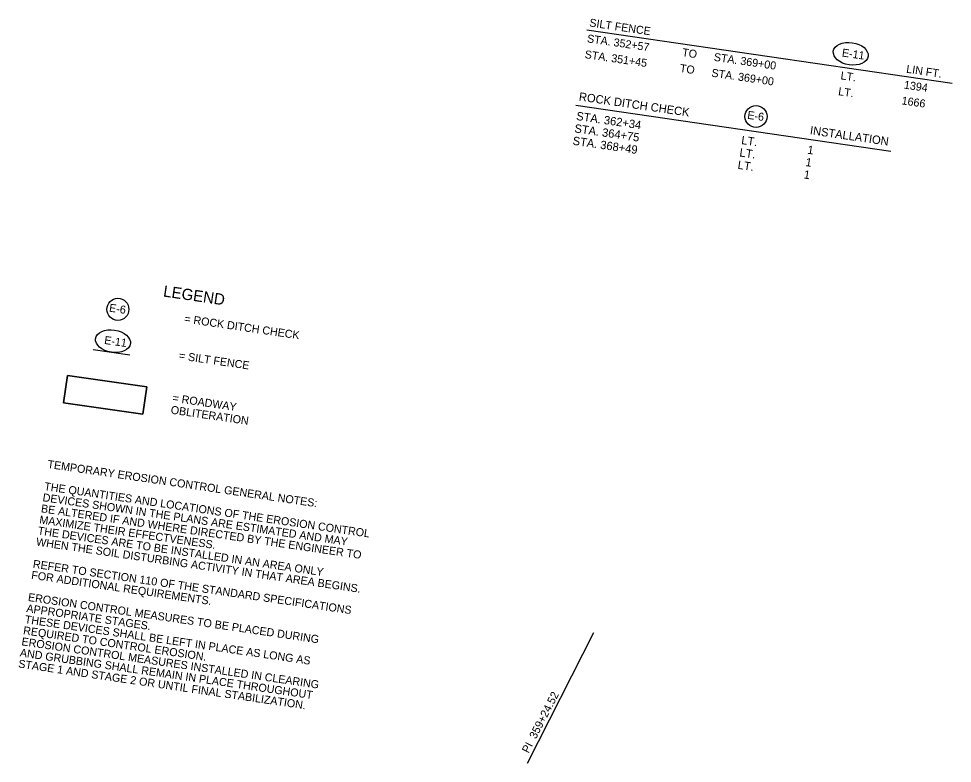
# Model space of a CAD drawing. Extents: x 882623 to 886086, y 1564278 to 1565583.
# Drawn here: x 884408 to 885107, y 1564440 to 1564998 of the extents above; entities that cross this region are included whole.
import ezdxf

# ---------------------------------------------------------------- set-up
doc = ezdxf.new("R2010")
doc.units = 0
for name, color, linetype in [('R_Annotation', 7, 'Continuous'), ('R_Draft', 7, 'Continuous'), ('R_Erosion', 7, 'Continuous'), ('R_Erosion_STG 2', 7, 'Continuous'), ('R_Horz Alg Annot', 7, 'Continuous')]:
    doc.layers.add(name, color=color, linetype=linetype)

msp = doc.modelspace()

# ---------------------------------------------------------------- linework, layer by layer
at = {"layer": 'R_Annotation'}
msp.add_line((884833.55, 1564989.99), (885107.46, 1564949.97), dxfattribs=at)
msp.add_lwpolyline([(884444.52, 1564731.01), (884503.77, 1564722.35), (884500.77, 1564701.85), (884441.52, 1564710.51)], close=True, dxfattribs=at)
at = {"layer": 'R_Draft'}
msp.add_lwpolyline([(884441.52, 1564710.51), (884500.77, 1564701.85), (884503.77, 1564722.35), (884444.52, 1564731.01), (884441.52, 1564710.51)], dxfattribs=at)
at = {"layer": 'R_Erosion'}
msp.add_lwpolyline([(884463.58, 1564750.33), (884491.09, 1564746.31)], dxfattribs=at)
for centre in [(884960.36, 1564925.1), (884482.16, 1564780.51)]:
    msp.add_circle(centre, 8.26, dxfattribs=at)
for centre in [(885031.3, 1564972.14), (884478.52, 1564756.64)]:
    msp.add_ellipse(centre, major_axis=(13.02, -1.85), ratio=0.638788, dxfattribs=at)
at = {"layer": 'R_Erosion_STG 2'}
msp.add_line((884825.45, 1564933.69), (885061.31, 1564899.23), dxfattribs=at)
at = {"layer": 'R_Horz Alg Annot'}
msp.add_lwpolyline([(884838.65, 1564537.97), (884788.78, 1564440.11)], dxfattribs=at)

# ---------------------------------------------------------------- texts
at = {"layer": 'R_Annotation'}
for s, p in [('SILT FENCE', (884835.17, 1564992.68)), ('STA. 352+57 ', (884833.43, 1564980.8)), ('STA. 351+45', (884831.7, 1564968.93)), ('TO', (884904.68, 1564970.4)), ('STA. 369+00', (884928.43, 1564966.93)), ('TO', (884902.94, 1564958.52)), ('LIN FT. ', (885072.65, 1564957.98)), ('STA. 369+00', (884926.69, 1564955.05)), ('LT.', (885023.42, 1564953.05)), ('1394', (885070.91, 1564946.11)), ('LT.', (885021.68, 1564941.17)), ('1666', (885069.18, 1564934.24)), ('TEMPORARY EROSION CONTROL GENERAL NOTES:', (884429.12, 1564661.65)), ('THE QUANTITIES AND LOCATIONS OF THE EROSION CONTROL', (884426.69, 1564645.02)), ('DEVICES SHOWN IN THE PLANS ARE ESTIMATED AND MAY', (884425.48, 1564636.71)), ('BE ALTERED IF AND WHERE DIRECTED BY THE ENGINEER TO', (884424.27, 1564628.4)), ('MAXIMIZE THEIR EFFECTVENESS.', (884423.05, 1564620.09)), ('THE DEVICES ARE TO BE INSTALLED IN AN AREA ONLY', (884421.84, 1564611.78)), ('WHEN THE SOIL DISTURBING ACTIVITY IN THAT AREA BEGINS.', (884420.62, 1564603.46)), ('REFER TO SECTION 110 OF THE STANDARD SPECIFICATIONS', (884418.19, 1564586.84)), ('FOR ADDITIONAL REQUIREMENTS.', (884416.98, 1564578.53)), ('EROSION CONTROL MEASURES TO BE PLACED DURING', (884414.55, 1564561.91)), ('APPROPRIATE STAGES. ', (884413.34, 1564553.59)), ('THESE DEVICES SHALL BE LEFT IN PLACE AS LONG AS', (884412.12, 1564545.28)), ('REQUIRED TO CONTROL EROSION.', (884410.91, 1564536.97)), ('EROSION CONTROL MEASURES INSTALLED IN CLEARING', (884409.69, 1564528.66)), ('AND GRUBBING SHALL REMAIN IN PLACE THROUGHOUT', (884408.48, 1564520.35)), ('STAGE 1 AND STAGE 2 OR UNTIL FINAL STABILIZATION.', (884407.27, 1564512.04))]:
    msp.add_text(s, height=6, rotation=351.68808, dxfattribs=at).set_placement(p)
at = {"layer": 'R_Erosion'}
for s, height, rotation, p in [('E-11', 5.999, 351.90245, (885024.45, 1564970.13)), ('E-6 ', 5.999, 352.08863, (884953.56, 1564923.41)), ('LEGEND', 8.439, 351.68809, (884515.78, 1564790.18)), ('E-6 ', 5.999, 352.08863, (884475.36, 1564778.82)), ('= ROCK DITCH CHECK', 6, 351.68809, (884531.63, 1564770.66)), ('E-11', 5.999, 351.90245, (884471.67, 1564754.63)), ('= SILT FENCE', 6, 351.68809, (884527.6, 1564743.07)), ('= ROADWAY ', 6, 351.68809, (884522.8, 1564711.29)), ('OBLITERATION', 6, 351.68809, (884521.5, 1564702.38))]:
    msp.add_text(s, height=height, rotation=rotation, dxfattribs=at).set_placement(p)
at = {"layer": 'R_Erosion_STG 2'}
for s, p in [('ROCK DITCH CHECK', (884827.33, 1564937.13)), ('STA. 362+34', (884825.34, 1564922.56)), ('STA. 364+75', (884823.98, 1564913.29)), ('INSTALLATION', (885000.49, 1564911.83)), ('STA. 368+49', (884822.63, 1564904.01)), ('LT.', (884949.02, 1564904.49)), ('LT.', (884947.67, 1564895.22)), ('1', (884998.5, 1564897.27)), ('1', (884997.14, 1564887.99)), ('LT.', (884946.31, 1564885.94)), ('1', (884995.79, 1564878.71))]:
    msp.add_text(s, height=6.25, rotation=351.68808, dxfattribs=at).set_placement(p)
at = {"layer": 'R_Horz Alg Annot'}
msp.add_text('PI  359+24.52', height=6, rotation=62.73976, dxfattribs=at).set_placement((884789.89, 1564447.24))

doc.saveas('drawing.dxf')
